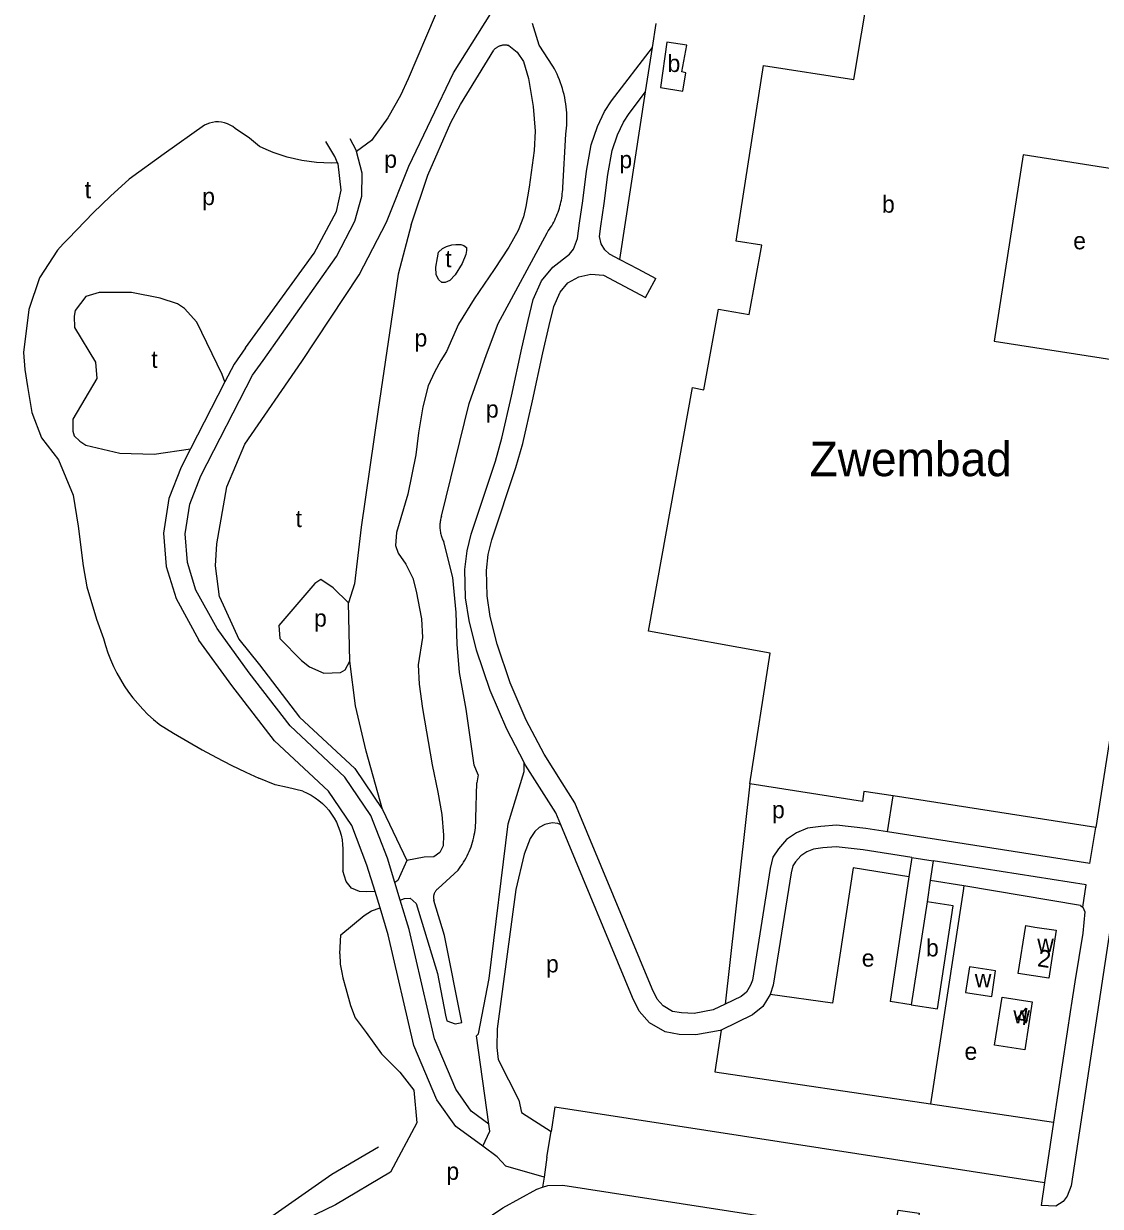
# Model space of a CAD drawing. Extents: x 161093 to 163177, y 379000 to 380904.
# Drawn here: x 161093.3 to 161343.5, y 380478.7 to 380753.5 of the extents above; entities that cross this region are included whole.
import ezdxf

# ---------------------------------------------------------------- set-up
doc = ezdxf.new("R2010")
doc.units = 0
for name, color, linetype in [('BLT_Basislijn', 7, 'Continuous'), ('BLT_Bebouwing', 7, 'Continuous'), ('BLT_Bebouwing_beschrifting', 7, 'Continuous'), ('BLT_Centroide', 7, 'Continuous'), ('BLT_Huisnummer', 7, 'Continuous'), ('BLT_Vlakafsluiter', 7, 'Continuous')]:
    doc.layers.add(name, color=color, linetype=linetype)

msp = doc.modelspace()

# ---------------------------------------------------------------- linework, layer by layer
at = {"layer": 'BLT_Basislijn'}
for p, q in [((161239.37, 380747.93), (161240.23, 380753.55)), ((161237.79, 380737.65), (161239.37, 380747.93)), ((161231.81, 380698.7), (161237.79, 380737.65)), ((161170.53, 380724.05), (161169.12, 380726.69)), ((161170.6, 380723.76), (161170.53, 380724.05)), ((161166.31, 380720.88), (161166.21, 380721.11)), ((161109.38, 380709.53), (161103.67, 380703.55)), ((161191.49, 380701.74), (161192.79, 380702.09)), ((161192.79, 380702.09), (161193.72, 380702.19)), ((161193.72, 380702.19), (161194.81, 380702.19)), ((161194.81, 380702.19), (161195.54, 380701.93)), ((161189.42, 380699.07), (161189.63, 380700.37)), ((161189.63, 380700.37), (161190.56, 380701.23)), ((161190.56, 380701.23), (161191.49, 380701.74)), ((161196.01, 380699.83), (161195.17, 380697.72)), ((161195.54, 380701.93), (161196.14, 380701.44)), ((161196.19, 380700.77), (161196.01, 380699.83)), ((161196.14, 380701.44), (161196.19, 380700.77)), ((161229.32, 380700.03), (161231.81, 380698.7)), ((161189.07, 380696.88), (161189.42, 380699.07)), ((161189.14, 380695.14), (161189.07, 380696.88)), ((161195.17, 380697.72), (161193.52, 380695.12)), ((161231.81, 380698.7), (161235.96, 380696.49)), ((161235.96, 380696.49), (161240.13, 380694.26)), ((161189.72, 380693.93), (161189.14, 380695.14)), ((161190.4, 380693.37), (161189.72, 380693.93)), ((161192.28, 380693.84), (161191.24, 380693.3)), ((161193.52, 380695.12), (161192.28, 380693.84)), ((161191.24, 380693.3), (161190.4, 380693.37)), ((161140.03, 380670.27), (161132.02, 380654.7)), ((161170.1, 380623.32), (161168.72, 380618.88)), ((161169.07, 380605.36), (161168.72, 380618.88)), ((161110.15, 380615.09), (161111.8, 380610.61)), ((161145.68, 380602.67), (161138.19, 380612.95)), ((161141.63, 380599.73), (161133.96, 380610.27)), ((161198.88, 380578.91), (161198.59, 380577.11)), ((161262.04, 380576.82), (161256.28, 380525.66)), ((161294.02, 380565.71), (161295.3, 380574.05)), ((161176.63, 380570.9), (161182.26, 380559.07)), ((161341.01, 380558.32), (161294.02, 380565.71)), ((161341.01, 380558.32), (161342.38, 380566.68)), ((161299.68, 380559.76), (161298.99, 380555.22)), ((161299.68, 380559.76), (161304.62, 380558.98)), ((161304.62, 380558.98), (161303.93, 380554.43)), ((161180.75, 380549.81), (161179.49, 380553.96)), ((161298.99, 380555.22), (161294.6, 380526.28)), ((161303.94, 380554.42), (161303.18, 380549.47)), ((161176.07, 380548.03), (161174.91, 380551.84)), ((161339.4, 380548.22), (161340.2, 380553.38)), ((161180.75, 380549.81), (161181.79, 380550.25)), ((161166.72, 380537.32), (161166.93, 380541.8)), ((161299.51, 380525.52), (161294.6, 380526.28)), ((161336.61, 380524.9), (161332.54, 380498.25)), ((161255.35, 380519.65), (161253.84, 380509.96)), ((161253.84, 380509.96), (161304.02, 380502.5)), ((161216.68, 380501.83), (161215.84, 380496.11)), ((161216.68, 380501.83), (161330.51, 380484.21)), ((161304.02, 380502.5), (161332.54, 380498.25)), ((161214.87, 380490.08), (161215.84, 380496.11)), ((161332.54, 380498.25), (161330.51, 380484.21)), ((161175.72, 380492.42), (161164.87, 380486.08)), ((161214.87, 380490.08), (161214.19, 380485.43)), ((161164.87, 380486.08), (161141.11, 380469.52)), ((161214.19, 380485.43), (161213.84, 380483.12)), ((161330.51, 380484.21), (161329.74, 380478.85))]:
    msp.add_line(p, q, dxfattribs=at)
for points in [[(161194.08, 380770.13), (161193.07, 380767.27), (161188.85, 380755.34), (161182.64, 380740.65), (161180.86, 380736.75), (161177.87, 380731.61), (161174.09, 380726.3), (161170.6, 380723.76)], [(161138.79, 380620.29), (161137.86, 380627.5), (161138.15, 380632.61), (161140.46, 380645.87), (161144.66, 380655.77), (161157.92, 380674.97), (161171.21, 380695.15), (161177.54, 380707.34), (161182.78, 380720.38), (161193.14, 380742.04), (161201.79, 380755.87)], [(161216.25, 380743.62), (161213.02, 380748.47), (161211.47, 380753.48)], [(161206, 380748.37), (161207.91, 380746.84), (161209.39, 380744.65), (161210.59, 380740.72), (161211.68, 380734.22), (161212.12, 380728.49), (161211.85, 380724.01), (161210.75, 380715.5), (161209.94, 380710.96), (161209.39, 380708.62), (161208.19, 380705.39), (161206, 380701.57), (161202.56, 380696.33), (161197.98, 380689.56), (161194.32, 380683.66), (161191.48, 380677.27), (161190.17, 380675.2), (161188.69, 380672.47), (161187.27, 380669.3), (161186.02, 380664.44), (161184.98, 380658.38), (161184.38, 380653.3), (161182.52, 380644.18), (161179.9, 380635.23), (161179.69, 380632.23), (161180.29, 380630.48), (161182.03, 380627.91), (161183.73, 380624.64), (161184.49, 380621.63), (161185.69, 380615.19), (161185.96, 380610.88), (161184.93, 380604.49), (161185.15, 380600.01), (161185.91, 380594.33), (161188.2, 380581.28), (161189.51, 380574.95), (161190.41, 380569.76), (161190.85, 380564.96), (161190.74, 380562.44), (161189.98, 380560.91), (161188.56, 380559.93), (161186.31, 380559.85), (161182.26, 380559.07)], [(161183.27, 380706.74), (161187.2, 380718.28), (161192.55, 380730.54), (161194.79, 380734.68), (161202.5, 380747.34)], [(161209.57, 380581.79), (161205.54, 380589.52), (161201.66, 380598.51), (161198.45, 380607.91), (161196.8, 380614.78), (161195.95, 380620.1), (161195.8, 380626.66), (161196.29, 380630.99), (161197.25, 380634.9), (161202.87, 380651.84), (161204.39, 380657.19), (161206.63, 380666.9), (161208.99, 380678.07), (161210.47, 380684.54), (161211.68, 380689.39), (161213.61, 380693.7), (161216.2, 380696.88), (161220.07, 380699.9), (161221.04, 380701.07), (161221.93, 380703.57), (161222.44, 380707.1), (161223.18, 380712.33), (161224.02, 380719.2), (161225.15, 380725.3), (161226.63, 380729.55), (161228.27, 380733.05), (161229.85, 380735.51), (161239.37, 380747.93)], [(161205.36, 380748.48), (161205.23, 380748.49), (161205.09, 380748.49), (161204.95, 380748.49), (161204.82, 380748.48), (161204.68, 380748.47), (161204.54, 380748.45), (161204.4, 380748.43), (161204.27, 380748.4), (161204.13, 380748.36), (161203.99, 380748.32), (161203.86, 380748.27), (161203.73, 380748.22), (161203.6, 380748.17), (161203.47, 380748.1), (161203.35, 380748.03), (161203.23, 380747.96), (161203.11, 380747.89), (161203, 380747.8), (161202.89, 380747.72), (161202.78, 380747.63), (161202.68, 380747.54), (161202.59, 380747.44), (161202.5, 380747.34)], [(161206, 380748.37), (161205.98, 380748.37), (161205.95, 380748.38), (161205.92, 380748.39), (161205.89, 380748.39), (161205.87, 380748.4), (161205.84, 380748.41), (161205.81, 380748.41), (161205.78, 380748.42), (161205.76, 380748.43), (161205.73, 380748.43), (161205.7, 380748.44), (161205.67, 380748.44), (161205.64, 380748.45), (161205.62, 380748.45), (161205.59, 380748.46), (161205.56, 380748.46), (161205.53, 380748.46), (161205.5, 380748.47), (161205.47, 380748.47), (161205.45, 380748.47), (161205.42, 380748.48), (161205.39, 380748.48), (161205.36, 380748.48)], [(161219.26, 380727.8), (161219.35, 380728.49), (161219.42, 380729.19), (161219.46, 380729.9), (161219.49, 380730.61), (161219.5, 380731.32), (161219.49, 380732.04), (161219.46, 380732.75), (161219.4, 380733.47), (161219.33, 380734.18), (161219.24, 380734.89), (161219.12, 380735.6), (161218.99, 380736.31), (161218.83, 380737.01), (161218.66, 380737.71), (161218.46, 380738.4), (161218.25, 380739.08), (161218.02, 380739.76), (161217.77, 380740.43), (161217.5, 380741.09), (161217.21, 380741.74), (161216.91, 380742.38), (161216.58, 380743), (161216.25, 380743.62)], [(161229.32, 380700.03), (161228.29, 380700.94), (161227.43, 380702.31), (161227.05, 380704.05), (161227.39, 380706.39), (161228.14, 380711.67), (161228.97, 380718.44), (161230, 380724.01), (161231.27, 380727.66), (161232.66, 380730.63), (161233.95, 380732.64), (161237.79, 380737.65)], [(161135.31, 380729.87), (161125.89, 380723.2), (161117.77, 380717.37)], [(161142.4, 380729.13), (161141.84, 380729.56), (161141.24, 380729.93), (161140.6, 380730.22), (161139.93, 380730.44), (161139.24, 380730.59), (161138.55, 380730.65), (161137.84, 380730.64), (161137.14, 380730.54), (161136.46, 380730.37), (161135.81, 380730.12), (161135.31, 380729.87)], [(161166.21, 380721.11), (161164.76, 380721.07), (161163.03, 380721.11), (161161.31, 380721.22), (161159.59, 380721.42), (161157.88, 380721.69), (161156.19, 380722.05), (161154.52, 380722.48), (161152.86, 380722.99), (161151.24, 380723.57), (161149.64, 380724.23), (161148.07, 380724.96), (161145.7, 380726.84), (161142.4, 380729.13)], [(161218.54, 380715.39), (161219.26, 380727.8)], [(161166.21, 380721.11), (161165.57, 380722.64), (161163.5, 380726.08)], [(161148.88, 380675.23), (161165.98, 380699.37), (161170.25, 380707.57), (161171.84, 380713.37), (161171.92, 380718.71), (161170.6, 380723.76)], [(161144.8, 380678.12), (161160.79, 380700.18), (161165.95, 380709.84), (161167.06, 380714.77), (161166.31, 380720.88)], [(161117.77, 380717.37), (161113.42, 380713.36), (161109.38, 380709.53)], [(161214.9, 380704.91), (161215.18, 380705.31), (161215.45, 380705.71), (161215.71, 380706.12), (161215.97, 380706.54), (161216.21, 380706.96), (161216.44, 380707.39), (161216.66, 380707.83), (161216.87, 380708.28), (161217.07, 380708.73), (161217.25, 380709.18), (161217.43, 380709.65), (161217.59, 380710.11), (161217.74, 380710.58), (161217.88, 380711.06), (161218, 380711.53), (161218.11, 380712.01), (161218.21, 380712.49), (161218.3, 380712.97), (161218.37, 380713.46), (161218.43, 380713.94), (161218.48, 380714.43), (161218.52, 380714.91), (161218.54, 380715.39)], [(161183.27, 380706.74), (161180.28, 380695.24), (161175.67, 380663.85)], [(161190.37, 380639.06), (161196.81, 380665.2), (161200.81, 380676.62), (161203.49, 380683.84), (161214.9, 380704.91)], [(161103.67, 380703.55), (161102.41, 380702.33), (161101.15, 380700.86), (161096.9, 380694.43), (161094.48, 380687.06), (161093.25, 380677.1), (161093.53, 380673.12), (161094.11, 380669.16), (161095.18, 380663.16), (161097.41, 380657.22), (161101.33, 380652.12), (161104.77, 380643.92), (161105.91, 380636.72), (161107.05, 380627.5), (161107.91, 380622.64), (161110.15, 380615.09)], [(161256.28, 380525.66), (161253.52, 380524.32), (161249.06, 380523.52), (161246.11, 380523.61), (161244.06, 380523.99), (161241.87, 380525.24), (161240.49, 380526.81), (161239.32, 380529.24), (161221.36, 380572.47), (161218.39, 380577.06), (161214.2, 380583.72), (161210.06, 380591.67), (161206.32, 380600.31), (161203.26, 380609.3), (161201.7, 380615.76), (161200.95, 380620.55), (161200.81, 380626.43), (161201.22, 380630.11), (161202.06, 380633.52), (161207.65, 380650.36), (161209.24, 380655.94), (161211.51, 380665.82), (161213.87, 380677), (161215.34, 380683.38), (161216.43, 380687.75), (161217.91, 380691.06), (161219.72, 380693.29), (161222.25, 380694.65), (161225.08, 380695.28), (161227.98, 380695.08)], [(161227.98, 380695.08), (161237.77, 380689.85), (161239.74, 380693.54)], [(161239.74, 380693.54), (161240.13, 380694.26)], [(161140.03, 380670.27), (161139.36, 380671.96), (161133.52, 380684.16), (161130.66, 380687.28), (161128.99, 380688.4), (161125.01, 380689.71), (161118.32, 380691.03), (161110.77, 380691.03), (161107.71, 380690.08), (161105.26, 380686.8), (161105.01, 380685.53), (161105.08, 380682.9), (161109.94, 380674.84), (161110.23, 380671.07), (161104.69, 380661.57), (161104.69, 380658.83), (161105.01, 380657.72), (161106.28, 380656.44), (161107.71, 380655.54), (161115.61, 380653.67), (161123.58, 380653.43), (161132.02, 380654.7)], [(161144.8, 380678.12), (161142.14, 380674.37), (161140.03, 380670.27)], [(161138.19, 380612.95), (161133.3, 380621.88), (161131.33, 380628.31), (161130.79, 380634.91), (161131.86, 380641.82), (161134.41, 380648.42), (161146.42, 380671.77), (161148.88, 380675.23)], [(161175.67, 380663.85), (161171.7, 380636.49), (161170.1, 380623.32)], [(161132.02, 380654.7), (161129.84, 380650.47), (161127, 380643.12), (161125.76, 380635.09), (161126.39, 380627.37), (161128.66, 380619.92), (161133.96, 380610.27)], [(161360.68, 380641.96), (161336.7, 380483.46), (161335.78, 380481.03), (161334.85, 380479.78), (161333.1, 380478.74), (161329.74, 380478.85)], [(161190.37, 380639.06), (161190.29, 380638.81), (161190.22, 380638.56), (161190.16, 380638.3), (161190.1, 380638.04), (161190.06, 380637.78), (161190.02, 380637.52), (161190, 380637.25), (161189.98, 380636.98), (161189.97, 380636.71), (161189.98, 380636.44), (161189.99, 380636.17), (161190.01, 380635.89), (161190.05, 380635.63), (161190.09, 380635.36), (161190.14, 380635.09), (161190.2, 380634.83), (161190.27, 380634.57), (161190.35, 380634.31), (161190.44, 380634.06), (161190.54, 380633.81), (161190.65, 380633.57), (161190.76, 380633.34), (161190.88, 380633.1)], [(161198.88, 380578.91), (161197.94, 380581.2), (161196.12, 380594.21), (161194.5, 380602.72), (161193.96, 380609.31), (161193.79, 380616.63), (161192.95, 380624.76), (161190.88, 380633.1)], [(161168.72, 380618.88), (161165.18, 380622.43), (161162.3, 380624.36), (161160.92, 380623.4), (161152.57, 380613.67), (161152.75, 380610.62), (161157.85, 380605.52), (161159.71, 380604.03), (161162.98, 380602.53), (161166.92, 380602.72), (161168, 380603.36), (161169.07, 380605.36)], [(161138.79, 380620.29), (161143.23, 380610.5), (161148.06, 380604.5), (161157.39, 380592.32), (161170.19, 380580.39), (161176.63, 380570.9)], [(161111.8, 380610.61), (161112.27, 380608.96), (161112.82, 380607.32), (161113.44, 380605.71), (161114.13, 380604.13), (161114.9, 380602.59), (161115.74, 380601.08), (161116.65, 380599.61), (161117.62, 380598.19), (161118.66, 380596.82), (161119.76, 380595.49), (161120.92, 380594.22), (161122.14, 380593), (161123.42, 380591.84), (161124.74, 380590.74), (161124.86, 380590.65)], [(161176.63, 380570.9), (161172.85, 380584.46), (161170.36, 380594.95), (161169.07, 380605.36)], [(161179.49, 380553.96), (161177.77, 380559.61), (161173.96, 380569.5), (161167.9, 380578.43), (161155.16, 380590.3), (161145.68, 380602.67)], [(161174.91, 380551.84), (161173.04, 380557.98), (161169.5, 380567.17), (161164.08, 380575.16), (161151.51, 380586.87), (161141.63, 380599.73)], [(161124.86, 380590.65), (161128.1, 380588.62), (161131.39, 380586.67), (161134.71, 380584.78), (161138.08, 380582.96), (161141.48, 380581.22), (161144.91, 380579.54), (161147.94, 380578.14)], [(161201.34, 380497.8), (161198.52, 380518.27), (161198.99, 380518.77), (161201.45, 380531.65), (161205.86, 380567.56), (161209.57, 380579.73), (161209.57, 380581.79)], [(161158.11, 380575.16), (161154.57, 380575.99), (161151.67, 380576.65), (161147.94, 380578.14)], [(161198.36, 380568.91), (161198.59, 380577.11)], [(161158.11, 380575.16), (161159.11, 380574.72), (161160.07, 380574.21), (161160.99, 380573.63), (161161.86, 380572.99), (161162.68, 380572.28), (161163.46, 380571.52), (161164.17, 380570.7), (161164.82, 380569.83), (161165.4, 380568.91), (161165.92, 380567.95), (161166.36, 380566.96), (161166.73, 380565.94), (161167.03, 380564.89), (161167.24, 380563.83), (161167.38, 380562.75), (161167.44, 380561.72)], [(161194.22, 380556.81), (161194.56, 380557.25), (161194.88, 380557.71), (161195.2, 380558.17), (161195.5, 380558.65), (161195.79, 380559.14), (161196.06, 380559.63), (161196.32, 380560.14), (161196.57, 380560.65), (161196.8, 380561.17), (161197.02, 380561.7), (161197.22, 380562.24), (161197.41, 380562.78), (161197.57, 380563.32), (161197.73, 380563.87), (161197.86, 380564.43), (161197.98, 380564.99), (161198.09, 380565.54), (161198.17, 380566.11), (161198.24, 380566.67), (161198.29, 380567.23), (161198.33, 380567.79), (161198.35, 380568.35), (161198.36, 380568.91)], [(161218.08, 380567.34), (161217.35, 380567.61), (161216.11, 380567.76), (161214.39, 380567.44), (161213.06, 380566.73), (161212.07, 380565.8), (161210.96, 380564.13), (161209.55, 380560.5), (161207.64, 380552.28), (161203.29, 380519.94), (161203.22, 380515.57), (161203.52, 380512.79), (161208.3, 380503.35), (161208.92, 380500.52), (161215.84, 380496.11)], [(161255.35, 380519.65), (161255.08, 380519.52), (161249.43, 380518.51), (161245.57, 380518.62), (161242.32, 380519.23), (161238.67, 380521.3), (161236.28, 380524.03), (161234.75, 380527.2), (161218.08, 380567.34)], [(161294.02, 380565.71), (161288.97, 380566.51), (161282.12, 380567.24), (161278.5, 380566.98), (161275.42, 380566.58), (161272.85, 380565.45), (161270.53, 380563.94), (161268.64, 380561.74), (161267.36, 380559.79), (161266.73, 380557.17), (161262.59, 380531.23), (161262.19, 380530.05), (161261.21, 380528.45), (161259.97, 380527.45), (161256.28, 380525.66)], [(161299.68, 380559.76), (161288.31, 380561.55), (161282.03, 380562.22), (161279, 380562.01), (161276.78, 380561.71), (161275.24, 380561.04), (161273.85, 380560.14), (161272.64, 380558.73), (161272.02, 380557.78), (161271.64, 380556.19), (161267.46, 380530.04), (161266.75, 380527.92), (161265.02, 380525.1), (161262.66, 380523.2), (161255.35, 380519.65)], [(161167.44, 380561.72), (161167.46, 380556.62)], [(161182.26, 380559.07), (161180.23, 380554.36), (161179.49, 380553.96)], [(161169.16, 380553.01), (161168.22, 380554.2), (161167.46, 380556.62)], [(161189.61, 380552.53), (161194.22, 380556.81)], [(161298.99, 380555.22), (161286.02, 380557.3), (161281.23, 380525.9), (161266.75, 380527.92)], [(161340.2, 380553.38), (161304.62, 380558.98)], [(161311.76, 380553.17), (161303.93, 380554.43)], [(161174.91, 380551.84), (161172.91, 380551.8), (161171.28, 380551.85), (161169.47, 380552.61), (161169.16, 380553.01)], [(161189.61, 380552.53), (161189.51, 380552.46), (161189.4, 380552.38), (161189.3, 380552.29), (161189.2, 380552.2), (161189.11, 380552.1), (161189.02, 380551.99), (161188.94, 380551.88), (161188.86, 380551.76), (161188.79, 380551.64), (161188.73, 380551.51), (161188.67, 380551.38), (161188.62, 380551.25), (161188.58, 380551.11), (161188.55, 380550.97), (161188.53, 380550.83), (161188.51, 380550.7), (161188.5, 380550.56), (161188.5, 380550.42), (161188.51, 380550.28), (161188.52, 380550.15), (161188.54, 380550.02), (161188.57, 380549.89), (161188.61, 380549.76)], [(161338.85, 380548.62), (161311.76, 380553.17), (161311.6, 380551.98), (161304.02, 380502.5)], [(161201.34, 380497.8), (161197.27, 380500.77), (161193.66, 380505.88), (161188.73, 380517.64), (161182.81, 380543.04), (161180.75, 380549.81)], [(161181.79, 380550.25), (161183.1, 380550.32), (161184.47, 380549.06), (161189.45, 380532.82), (161191.27, 380523.07), (161191.63, 380521.77), (161193.53, 380521.13), (161195.1, 380521.42)], [(161195.1, 380521.42), (161191.03, 380541.63), (161188.61, 380549.76)], [(161339.4, 380548.22), (161339.84, 380547.11), (161339.35, 380542.18), (161337.54, 380530.82)], [(161338.85, 380548.62), (161339.4, 380548.22)], [(161166.93, 380541.8), (161172.37, 380546.23), (161174.12, 380547.32), (161176.07, 380548.03)], [(161199.93, 380492.64), (161193.66, 380497.21), (161189.26, 380503.44), (161183.96, 380516.09), (161177.98, 380541.75), (161176.07, 380548.03)], [(161166.72, 380537.32), (161166.84, 380534.93), (161167.18, 380533), (161167.44, 380531.76)], [(161167.44, 380531.76), (161168.09, 380529.32), (161169.24, 380525.36), (161170.3, 380522.52), (161172.83, 380519.06), (161176.39, 380514.13), (161180.68, 380509.86), (161183.93, 380505.69), (161184.65, 380498.1)], [(161337.54, 380530.82), (161336.68, 380525.38), (161336.61, 380524.9)], [(161184.65, 380498.1), (161178.49, 380486.62), (161165.7, 380479.06), (161156.61, 380474.6), (161137.07, 380447.48)], [(161199.93, 380492.64), (161201.57, 380496.18), (161201.34, 380497.8)], [(161214.19, 380485.43), (161205.34, 380488.05), (161203.29, 380490.19), (161199.93, 380492.64)], [(161137.07, 380447.48), (161144.71, 380448.17), (161157.32, 380451.01), (161170.13, 380455.89), (161181.11, 380461.31), (161190.23, 380468.57), (161204.57, 380478.35), (161212.5, 380482.66), (161213.84, 380483.12)], [(161213.84, 380483.12), (161215.09, 380483.55), (161218.52, 380483.64), (161295.56, 380471.7), (161296.49, 380477.82), (161301.35, 380477.09), (161300.47, 380470.93), (161328.98, 380466.5), (161329.9, 380472.69), (161334.48, 380471.98), (161335.13, 380471.86), (161352.54, 380469.32), (161354.21, 380468.64), (161355.48, 380467.36), (161355.94, 380465.82), (161356, 380464.58), (161355.58, 380461.89)]]:
    msp.add_lwpolyline(points, dxfattribs=at)
at = {"layer": 'BLT_Bebouwing'}
for p, q in [((161325.55, 380722.99), (161318.78, 380679.71)), ((161352.34, 380718.78), (161325.55, 380722.99)), ((161318.78, 380679.71), (161351.02, 380674.65)), ((161352.04, 380628.38), (161342.38, 380566.68)), ((161331.47, 380531.68), (161324.39, 380532.78)), ((161320.62, 380527.26), (161327.61, 380526.17)), ((161305.63, 380524.59), (161305.63, 380524.59))]:
    msp.add_line(p, q, dxfattribs=at)
for points in [[(161262.04, 380576.82), (161266.7, 380607.19), (161238.48, 380612.29), (161248.7, 380668.91), (161251.34, 380668.43), (161254.72, 380687.17), (161261.86, 380685.88), (161264.78, 380702.03), (161258.81, 380702.96), (161265.16, 380743.79), (161286.19, 380740.52), (161291.52, 380772.43), (161342.69, 380763.87), (161344.54, 380775.72)], [(161295.3, 380574.05), (161288.53, 380575.11), (161288.16, 380572.76), (161262.04, 380576.82)], [(161342.38, 380566.68), (161295.3, 380574.05)], [(161299.51, 380525.52), (161305.63, 380524.59), (161309.29, 380548.53), (161303.18, 380549.47)], [(161303.18, 380549.47), (161299.51, 380525.52)], [(161324.39, 380532.78), (161326.12, 380543.92), (161328.26, 380543.59), (161333.2, 380542.82), (161331.47, 380531.68)], [(161327.61, 380526.17), (161325.89, 380515.08), (161318.9, 380516.16), (161320.62, 380527.26)]]:
    msp.add_lwpolyline(points, dxfattribs=at)
for points in [[(161246.46, 380737.8), (161247.15, 380742.06), (161246.22, 380742.27), (161247.34, 380748.46), (161242.69, 380749.2), (161241.21, 380738.67)], [(161313.05, 380534.3), (161312.14, 380528.41), (161318.23, 380527.48), (161319.13, 380533.37)]]:
    msp.add_lwpolyline(points, close=True, dxfattribs=at)
at = {"layer": 'BLT_Vlakafsluiter'}
msp.add_lwpolyline([(161218.08, 380567.34), (161216.92, 380570.13), (161214.18, 380574.36), (161209.86, 380581.23), (161209.57, 380581.79)], dxfattribs=at)

# ---------------------------------------------------------------- texts
at = {"layer": 'BLT_Bebouwing_beschrifting'}
msp.add_text('Zwembad', height=8, dxfattribs=at).set_placement((161275.9, 380648.34))
at = {"layer": 'BLT_Centroide'}
for s, p in [('b', (161242.88, 380742.25)), ('p', (161177.05, 380719.99)), ('p', (161231.68, 380719.9)), ('t', (161107.45, 380712.9)), ('p', (161134.74, 380711.33)), ('b', (161292.71, 380709.56)), ('e', (161337.15, 380701.05)), ('t', (161191.22, 380696.88)), ('p', (161184.08, 380678.46)), ('t', (161122.91, 380673.5)), ('p', (161200.67, 380661.94)), ('t', (161156.45, 380636.51)), ('p', (161160.73, 380613.38)), ('p', (161267.15, 380568.85)), ('b', (161302.94, 380536.75)), ('w', (161328.8, 380537.8)), ('e', (161288.01, 380534.38)), ('p', (161214.63, 380533.04)), ('w', (161314.28, 380529.6)), ('w', (161323.25, 380521.17)), ('e', (161311.89, 380512.72)), ('p', (161191.49, 380484.85))]:
    msp.add_text(s, height=4, dxfattribs=at).set_placement(p)
at = {"layer": 'BLT_Huisnummer'}
for s, rotation, p in [('2', 351.1675, (161328.67, 380534.5)), ('4', 351.1769, (161323.64, 380521.16))]:
    msp.add_text(s, height=4, rotation=rotation, dxfattribs=at).set_placement(p)

doc.saveas('drawing.dxf')
